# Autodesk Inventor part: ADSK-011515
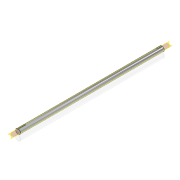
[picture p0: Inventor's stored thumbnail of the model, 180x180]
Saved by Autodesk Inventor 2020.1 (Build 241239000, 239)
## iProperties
Created: 1999-12
Part Number: ADSK-011515
Material: Acier doux
Document SubType Name: Modeling
Designer: sspink
Density: 7.86 g/cm^3
Appearance: Chrom - poliert
Mass: 1402.65 g
Surface Area: 365.634 cm^2
Volume: 178.454 cm^3
Control State: 0
Master: False
Checked Out: False
Shininess: 0.0
Length Units: 11269
Angle Units: 11279
Time Units: 11290
Mass Units: 11283
Length Display Precision: 3
Angle Display Precision: 2
Compacted: True
Dimensions: 20x20x570 mm
Mass: 1,403 kg
DocNumber: ADSK-011515.ipt
Folder: 01 - Themengebiete\Simplification\01 - Packaging machine\
VDS_Category: 3D Komponenten
Density: 0.0
Volumn: 0.0
Area: 0.0
PropertySet Name: Model Information
Author: sspink
Revision Number: -
Title: shaft
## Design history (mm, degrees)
node "Extrusion2" dims "d7" = 30, "d8" = 0
  sketch "Sketch4"
    geometry: L1 (0, 0)-(0, 10); L2 (0, 7.5)-(2.5, 7.5); L3 (2.5, 7.5)-(2.5, 11.5); L4 (2.5, 11.5)-(-2.5, 11.5); L5 (-2.5, 11.5)-(-2.5, 7.5); L6 (-2.5, 7.5)-(0, 7.5)
    constraints: 12 end point, 2 collinear, 2 parallel, 2 perpendicular, 1 point on line, 1 vertical, 1 vertical alignment, 1 other
    dimensions: "d4" = 2.5 distance from line of L1.end L2; "d5" = 4 distance of L4.end L5.end; "d6" = 2.5 distance of L5.end L2.start (= d4)
chamfer "Fase1" distance "d9" = 1; stored, may be unused: second distance "d10" = 2, angle "d11" = 45 deg
fillet "Rundung1"
workplane "Arbeitsebene2"
sketch "Skizze5"
  geometry: L1 (-10, 0)-(10, 0) reference; L2 (-2.5, 0)-(-2.5, 20); L3 (2.5, 20)-(2.5, 0); A1 r 2.5 centre (0, 20) between (2.5, 20) and (-2.5, 20); 2 further points
  constraints: 4 end point, 2 perpendicular, 2 point on circle, 2 point on line, 2 tangent, 1 centre point, 1 midpoint, 1 vertical alignment
  dimensions: "d12" = 20 distance of L2.start L2.end; "d13" = 2.5 radius of A1
extrude "Extrusion3" cut sketch "Skizze5" distance "d14" = 2; taper "d15" = 0 deg
node "Solide1"
  node "Extrusion1" dims "d1" = 570, "d2" = 0
sketch "Sketch1"
  geometry: C1 r 10 at (0, 0); 1 further point
  constraints: 1 centre point, 1 coincident
  dimensions: "d0" = 20 diameter of C1
workplane "Work Plane1"
node "Corps solides"
node "Corps surfaciques"
other parameters: "d3" = -114.3
